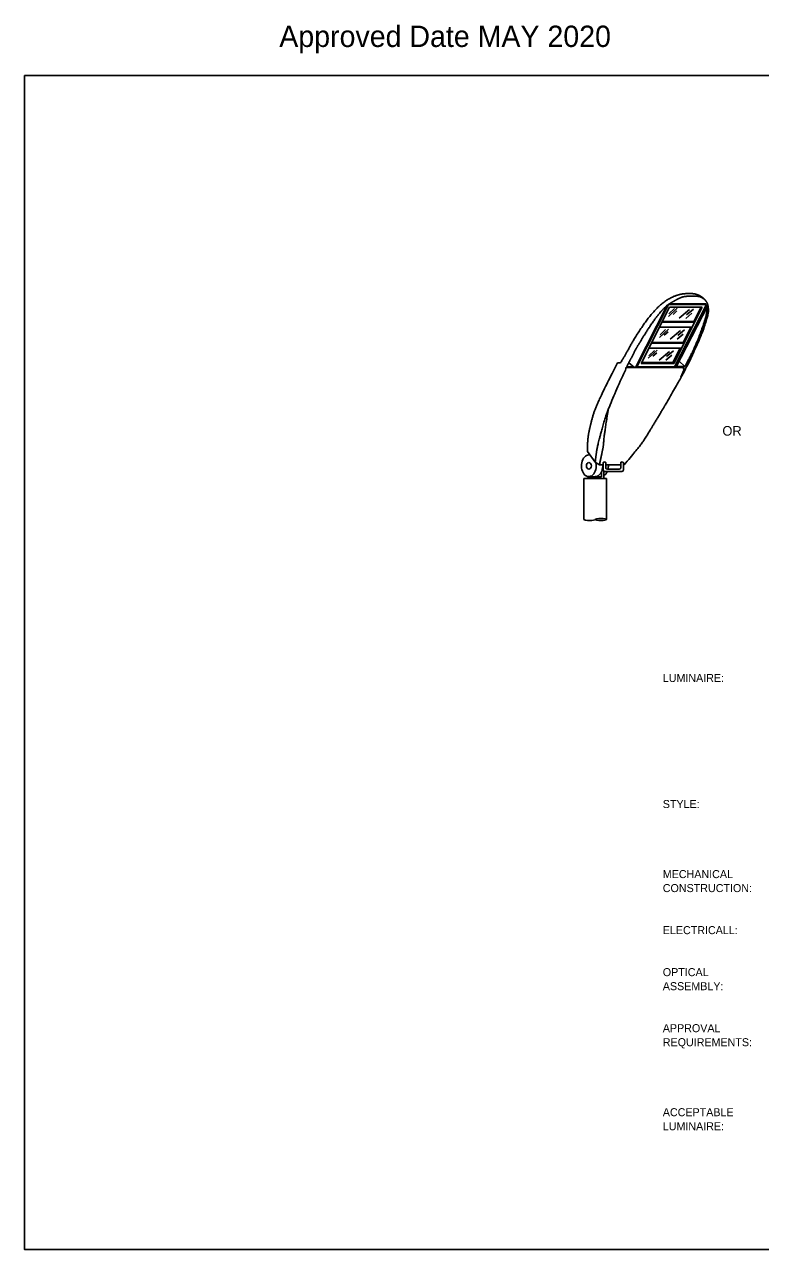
# Model space of a CAD drawing. Extents: x 99981 to 128681, y 99783 to 102182.
# Drawn here: x 110181 to 111560, y 99887 to 102182 of the extents above; entities that cross this region are included whole.
import ezdxf

# ---------------------------------------------------------------- set-up
doc = ezdxf.new("R2010")
doc.units = 0
for name, color, linetype in [('Default', 7, 'Continuous'), ('Level 1', 7, 'Continuous'), ('Notes Tabular Notes', 7, 'Continuous'), ('RD Standard Plans Active', 7, 'Continuous')]:
    doc.layers.add(name, color=color, linetype=linetype)

msp = doc.modelspace()

# ---------------------------------------------------------------- linework, layer by layer
at = {"layer": 'Default'}
msp.add_lwpolyline([(110181.4, 102086.3), (113381.1, 102086.3), (113381.1, 99886.7), (110181.4, 99886.7)], close=True, dxfattribs=at)
at = {"layer": 'Notes Tabular Notes'}
for p, q in [((111326.1, 101539.3), (111385.9, 101656)), ((111388.4, 101657.3), (111328.7, 101540.9)), ((111336.7, 101547.1), (111390.1, 101652.7)), ((111404.6, 101650.6), (111387.8, 101635.1)), ((111459.3, 101657.3), (111388.4, 101657.3)), ((111399.3, 101649.7), (111388.9, 101639.8)), ((111390.1, 101652.7), (111451.4, 101652.7)), ((111457.9, 101658.9), (111390.2, 101658.9)), ((111404, 101645.7), (111396.7, 101638.9)), ((111397.9, 101547.1), (111451.4, 101652.7)), ((111459.3, 101657.3), (111399.4, 101540.9)), ((111462.1, 101655.9), (111401.8, 101539.3)), ((111427.4, 101648.2), (111408, 101631.7)), ((111421.9, 101638.3), (111434.9, 101648.9)), ((111435.7, 101625.9), (111449.3, 101652.7)), ((111459.3, 101657.3), (111457.9, 101658.9)), ((111375.8, 101624.3), (111437, 101624.3)), ((111376.6, 101625.9), (111435.7, 101625.9)), ((111432.1, 101641), (111420.8, 101631.5)), ((111437, 101624.3), (111435.7, 101625.9)), ((111371, 101614.9), (111432.3, 101614.9)), ((111388, 101611.4), (111371.2, 101595.9)), ((111382.7, 101610.4), (111372.3, 101600.6)), ((111387.4, 101606.5), (111380.1, 101599.7)), ((111410.8, 101608.9), (111391.4, 101592.5)), ((111415.5, 101601.7), (111404.2, 101592.3)), ((111405.3, 101599.1), (111418.3, 101609.7)), ((111415.7, 101586.5), (111430.1, 101614.9)), ((111351.1, 101575.5), (111412.3, 101575.5)), ((111355.9, 101584.9), (111417.1, 101584.9)), ((111356.6, 101586.5), (111415.7, 101586.5)), ((111396.5, 101548.7), (111410.1, 101575.5)), ((111417.1, 101584.9), (111415.7, 101586.5)), ((111366.9, 101572.1), (111350.1, 101556.6)), ((111361.6, 101571.2), (111351.2, 101561.4)), ((111366.3, 101567.2), (111358.9, 101560.4)), ((111389.7, 101569.7), (111370.3, 101553.2)), ((111394.4, 101562.5), (111383.1, 101553.1)), ((111384.2, 101559.9), (111397.2, 101570.4)), ((111298.2, 101548.1), (111292.5, 101548.1)), ((111308.6, 101539.5), (111309.8, 101540.9)), ((111416.1, 101539.5), (111308.6, 101539.5)), ((111322.3, 101540.9), (111309.8, 101540.9)), ((111313.6, 101548.1), (111324.2, 101539.3)), ((111401.8, 101539.3), (111324.2, 101539.3)), ((111399.4, 101540.9), (111328.7, 101540.9)), ((111336.7, 101547.1), (111397.9, 101547.1)), ((111337.4, 101548.7), (111396.5, 101548.7)), ((111397.9, 101547.1), (111396.5, 101548.7)), ((111397.9, 101547.1), (111397.9, 101547.1)), ((111401.8, 101539.3), (111399.9, 101541.7)), ((111402.8, 101541.2), (111419.1, 101541.2)), ((111419, 101541.2), (111407.8, 101551)), ((111416.9, 101534.5), (111411.5, 101521)), ((111250.8, 101362.1), (111236.2, 101382.1)), ((111258.6, 101356.8), (111250.8, 101362.1)), ((111258.6, 101356.8), (111265.8, 101356.8)), ((111265.8, 101361.6), (111265.8, 101347.4)), ((111270.5, 101361.6), (111270.5, 101350.5)), ((111270.5, 101356.8), (111298.8, 101356.8)), ((111273.6, 101349), (111295.6, 101349)), ((111298.8, 101361.6), (111298.8, 101350.5)), ((111303.5, 101361.6), (111303.5, 101347.4)), ((111303.5, 101356.8), (111304.9, 101356.8)), ((111229.6, 101331.7), (111229.6, 101254.6)), ((111229.6, 101331.7), (111272, 101331.7)), ((111262.6, 101334.8), (111237.4, 101334.8)), ((111237.4, 101334.8), (111237.4, 101331.7)), ((111262.6, 101334.8), (111262.6, 101344.2)), ((111267.2, 101331.7), (111267.2, 101344.7)), ((111300.4, 101344.3), (111268.9, 101344.3)), ((111272, 101331.7), (111272, 101254.6))]:
    msp.add_line(p, q, dxfattribs=at)
for centre, radius, start, end in [((111268.9, 101347.4), 3.12, 180, 270), ((111300.4, 101347.4), 3.13, 270, 0)]:
    msp.add_arc(centre, radius, start, end, dxfattribs=at)
for centre, major_axis, ratio, start_param, end_param in [((111238.9, 101355.3), (0, 20.4), 0.680224, 6.131696, 11.280191), ((111251, 101355.3), (0, 20.4), 0.680224, 3.141593, 4.782131), ((111268.1, 101361.6), (2.34, 0), 0.345998, 0, 3.141988), ((111273.6, 101350.5), (-3.15, 0), 0.485174, 0, 1.570796), ((111261.5, 101355.3), (0, 20.4), 0.680224, 4.393196, 4.782131), ((111295.6, 101350.5), (3.16, 0), 0.482871, 4.712389, 6.283185), ((111301.1, 101361.6), (2.34, 0), 0.345998, 6.28279, 9.424778), ((111261.5, 101355.3), (0, 20.4), 0.680224, 3.567544, 4.136609), ((111240.2, 101254.6), (10.6, 0), 0.165832, 3.141593, 6.283185)]:
    msp.add_ellipse(centre, major_axis=major_axis, ratio=ratio, start_param=start_param, end_param=end_param, dxfattribs=at)
for centre, major_axis, ratio in [((111238.9, 101355.3), (0, 6.26), 0.750452), ((111261.4, 101254.6), (10.6, 0), 0.165832)]:
    msp.add_ellipse(centre, major_axis=major_axis, ratio=ratio, dxfattribs=at)
for points, degree in [([(111298.2, 101548.1), (111307.8, 101563.8), (111320, 101586.8), (111337.2, 101613.9), (111354.9, 101638.3), (111376.6, 101660.9), (111397.1, 101672.8), (111415.6, 101678.1), (111438.4, 101678.1), (111454.1, 101670.5), (111458.2, 101663.8)], 2), ([(111309.8, 101540.9), (111316.9, 101554.4), (111327.3, 101574.7), (111336.9, 101590.5), (111348.5, 101609.4), (111364.7, 101633.4), (111378.9, 101649.9), (111386.4, 101656.9), (111399.7, 101664.6), (111410.9, 101670.6), (111420.3, 101673), (111434.8, 101673), (111444.8, 101673), (111453.8, 101669), (111460.2, 101661.7), (111462.1, 101655.9), (111463.2, 101646.9), (111462, 101637.3), (111452.1, 101605.5), (111433.1, 101562.8), (111418.5, 101532.7), (111383.7, 101471.8), (111343.8, 101405.3), (111333, 101390.2), (111304.9, 101356.8)], 2), ([(111419.1, 101541.2), (111428.8, 101559.5), (111440.5, 101584.9), (111448.9, 101606.4), (111457.4, 101630.9), (111459.9, 101643.6), (111461.1, 101654)], 2), ([(111236.2, 101382.1), (111236.2, 101404.5), (111241, 101428.1), (111248.3, 101456.7), (111263, 101490), (111292.5, 101548.1)], 2), ([(111250.8, 101362.1), (111252.8, 101380.5), (111257.1, 101400.8), (111274.9, 101465.4), (111307.3, 101534.6)], 2), ([(111308.6, 101539.5), (111308.7, 101537.8), (111307.3, 101534.6), (111308.6, 101539.5), (111307.3, 101534.6)], 3), ([(111416.1, 101539.5), (111416.9, 101537.9), (111416.9, 101534.5), (111416.1, 101539.5), (111416.9, 101534.5)], 3), ([(111258.6, 101356.8), (111263.1, 101377.9), (111266.2, 101392.3), (111267.7, 101414.8), (111275, 101458.6)], 2)]:
    msp.add_open_spline(points, degree=degree, dxfattribs=at)

# ---------------------------------------------------------------- texts
at = {"layer": 'Level 1'}
for s, height, p in [('OR', 18, (111489.1, 101411.7)), ('LUMINAIRE:', 15, (111377.4, 100950.1)), ('STYLE:', 15, (111377.4, 100713.9)), ('MECHANICAL ', 15, (111377.4, 100582.6)), ('CONSTRUCTION:', 15, (111377.4, 100556.4)), ('ELECTRICALL:', 15, (111377.4, 100477.6)), ('OPTICAL ', 15, (111377.4, 100398.9)), ('ASSEMBLY:', 15, (111377.4, 100372.6)), ('APPROVAL ', 15, (111377.4, 100293.9)), ('REQUIREMENTS:', 15, (111377.4, 100267.6)), ('ACCEPTABLE ', 15, (111377.4, 100136.4)), ('LUMINAIRE:', 15, (111377.4, 100110.1))]:
    msp.add_text(s, height=height, dxfattribs=at).set_placement(p)
at = {"layer": 'RD Standard Plans Active'}
msp.add_text('Approved Date MAY 2020', height=40, dxfattribs=at).set_placement((110658.8, 102140))

doc.saveas('drawing.dxf')
